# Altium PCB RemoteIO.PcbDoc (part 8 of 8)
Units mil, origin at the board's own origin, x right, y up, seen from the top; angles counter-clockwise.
Board outline 7874.02 x 2362.2 mil, 6 copper layers (Top Layer, GND1, Layer 2, PWR, GND2, Bottom Layer), stack 60.956 mil thick; 655 components, 447 nets, 2607 pads, 1444 vias.
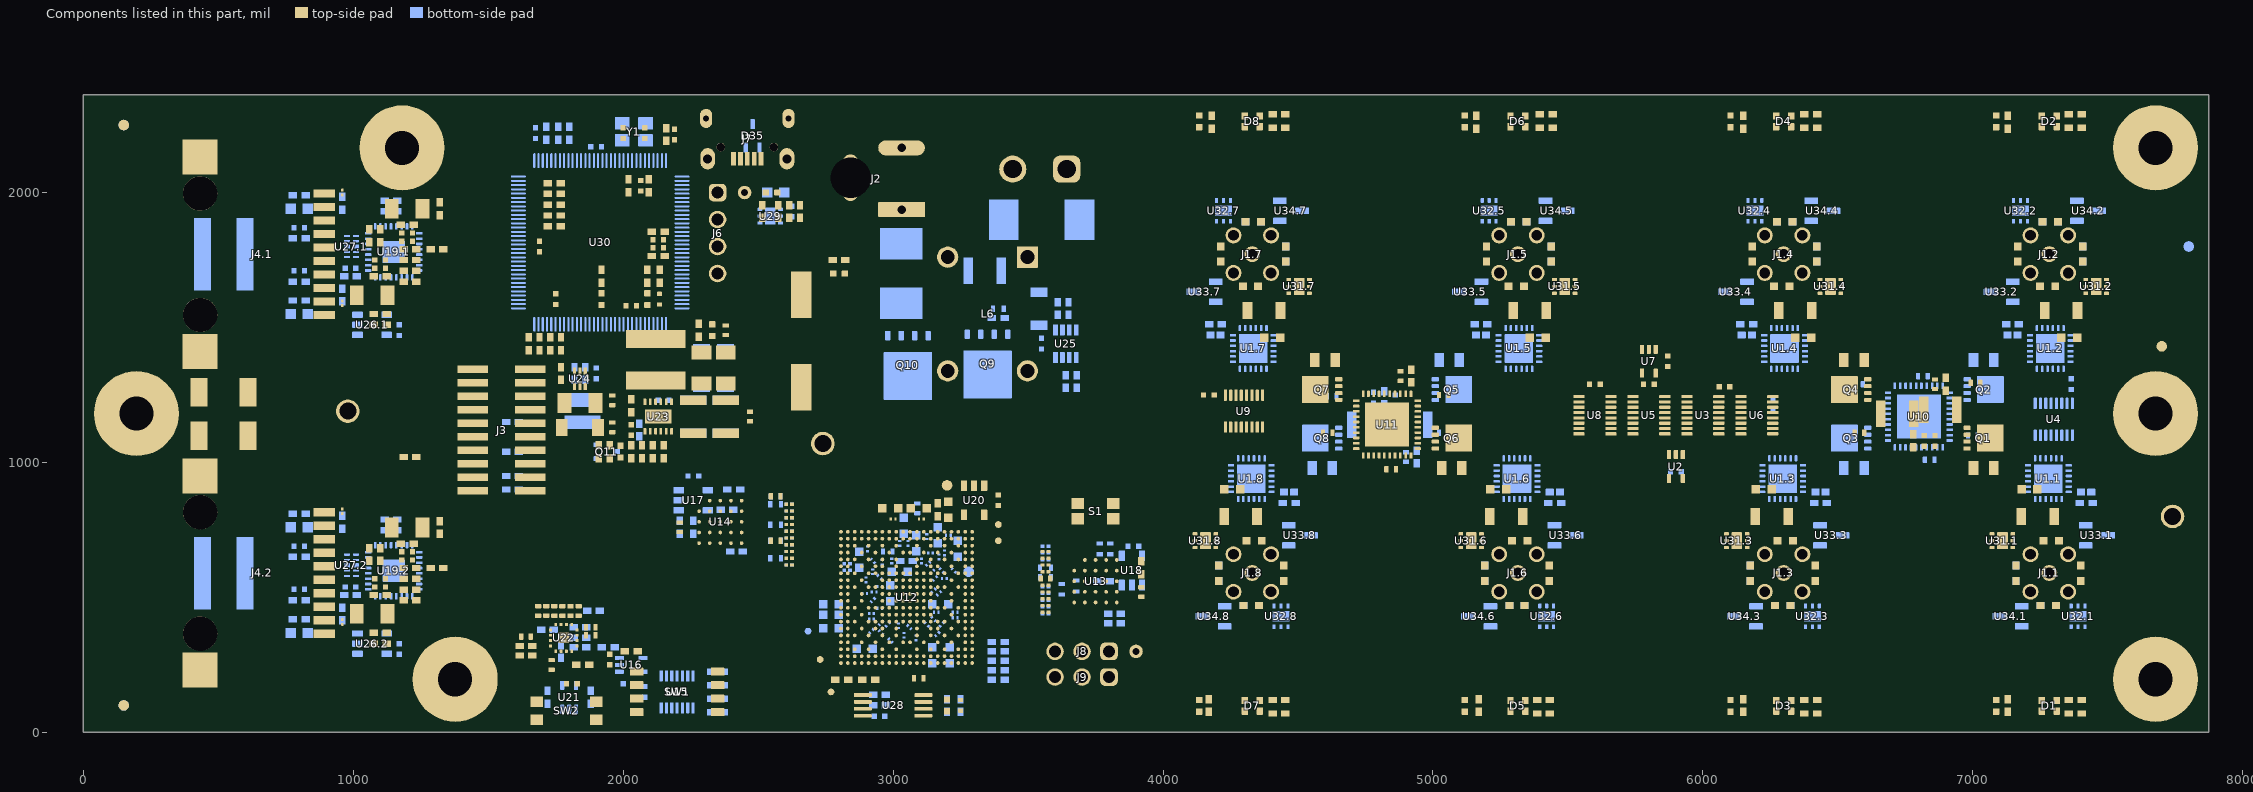
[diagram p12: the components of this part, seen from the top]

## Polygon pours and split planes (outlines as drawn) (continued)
NetQ3_1 on Bottom Layer "BOTTOM_LAYER_NETQ3_1_P293" (solid, remove dead copper, pour order 293): 6700,1130 6700,1090 6670,1090 6645,1065 6580,1065 6580,1140 6625,1140 6635,1130
24V on Bottom Layer "BOTTOM_LAYER_24V_P288" (solid, remove dead copper, pour order 288): 6700,1211.25 6700,1128.75 6590,1128.75 6590,1211.25
GND on Bottom Layer "BOTTOM_LAYER_GND_P286" (solid, remove dead copper, pour order 286): 5000,1410 5045,1410 5045,1330 5000,1330
L+5 on Bottom Layer "BOTTOM_LAYER_L+5_P284" (solid, remove dead copper, pour order 284): 5045,1205 5150,1205 5150,1410 5075,1410 5075,1350 5045,1320
NetQ5_1 on Bottom Layer "BOTTOM_LAYER_NETQ5_1_P283" (solid, remove dead copper, pour order 283): 4985,1290 5040,1290 5040,1205 4985,1205
GND on Bottom Layer "BOTTOM_LAYER_GND_P280" (solid, remove dead copper, pour order 280): 4740,1235 4925,1235 4965,1195 4965,1020 4745,1020 4740,1025
CS1 on Bottom Layer "BOTTOM_LAYER_CS1_P278" (solid, remove dead copper, pour order 278): 5045,1140 5145,1140 5145,1040 5045,1040
NetQ6_1 on Bottom Layer "BOTTOM_LAYER_NETQ6_1_P276" (solid, remove dead copper, pour order 276): 5010,1135 5010,1080 5045,1080 5045,1135
24V on Bottom Layer "BOTTOM_LAYER_24V_P275" (solid, remove dead copper, pour order 275): 5010,1090 5010,1135 5020,1145 5045,1145 5045,1195 4960,1195 4960,1090
24V on Bottom Layer "BOTTOM_LAYER_24V_P271" (solid, remove dead copper, pour order 271): 4635,1195 4635,1135 4660,1135 4680,1115 4680,1085 4700,1085 4740,1085 4740,1195
GND on Bottom Layer "BOTTOM_LAYER_GND_P269" (solid, remove dead copper, pour order 269): 4670,1010.14 4670,950.14 4605,950.14 4605,1010.14
L+8 on Bottom Layer "BOTTOM_LAYER_L+8_P267" (solid, remove dead copper, pour order 267): 4515,1140 4615,1140 4615,1040 4580,1005 4580,950 4515,950
NetQ8_1 on Bottom Layer "BOTTOM_LAYER_NETQ8_1_P265" (solid, remove dead copper, pour order 265): 4620,1145 4650,1145 4665,1130 4675,1120 4675,1065 4620,1065
L+7 on Bottom Layer "BOTTOM_LAYER_L+7_P087" (solid, remove dead copper, pour order 87): 4515,1220 4620,1220 4620,1320 4515,1320
NetQ7_1 on Bottom Layer "BOTTOM_LAYER_NETQ7_1_P263" (solid, remove dead copper, pour order 263): 4625,1275 4675,1275 4700,1250 4700,1205 4645,1205 4625,1225
GND on Bottom Layer "BOTTOM_LAYER_GND_P262" (solid, remove dead copper, pour order 262): 2470,1850 2470,2025 2675,2025 2675,1850
+3V3_XDS110 on Bottom Layer "BOTTOM_LAYER_+3V3_XDS110_P088" (solid, remove dead copper, pour order 88): 2025,1480 2070,1480 2070,1570 2025,1570
GND on Bottom Layer "BOTTOM_LAYER_GND_P256" (solid, remove dead copper, pour order 256): 7020,1410 7020,1350 6960,1350 6960,1410
L+2 on Bottom Layer "BOTTOM_LAYER_L+2_P252" (solid, remove dead copper, pour order 252): 7015,1220 7120,1220 7120,1410 7040,1410 7040,1345 7015,1320
NetQ2_1 on Bottom Layer "BOTTOM_LAYER_NETQ2_1_P251" (solid, remove dead copper, pour order 251): 6900,1245 6925,1245 6935,1255 6935,1275 6950,1290 7000,1290 7000,1225 6985,1210 6900,1210
24V on Bottom Layer "BOTTOM_LAYER_24V_P250" (solid, remove dead copper, pour order 250): 7005,1210 7005,1127.5 6895,1127.5 6895,1210
L+1 on Bottom Layer "BOTTOM_LAYER_L+1_P247" (solid, remove dead copper, pour order 247): 7005,1145 7115,1145 7115,1040 7005,1040
NetQ1_1 on Bottom Layer "BOTTOM_LAYER_NETQ1_1_P245" (solid, remove dead copper, pour order 245): 6900,1134.05 6900,1095 6930,1095 6945,1080 7000,1080 7000,1134.05
NetJ1.8_4 on Bottom Layer "BOTTOM_LAYER_NETJ1.8_4_P184" (solid, remove dead copper, pour order 184): 4192.24,375 4327.24,375 4327.24,550 4192.24,550
GND on Bottom Layer "BOTTOM_LAYER_GND_P200" (solid, remove dead copper, pour order 200): 4332.24,375 4502.24,375 4502.24,585 4332.24,585
NetU31.8_4 on Bottom Layer "BOTTOM_LAYER_NETU31.8_4_P102" (solid, remove dead copper, pour order 102): 4397.24,405 4397.24,375 4187.24,375 4187.24,595 4139.74,642.5 4139.74,750 4077.24,750 4077.24,400 4077.24,330 4497.24,330 4577.24,410 4577.24,745 4507.24,745 4507.24,425 4487.24,405
NetJ1.8_2 on Bottom Layer "BOTTOM_LAYER_NETJ1.8_2_P216" (solid, remove dead copper, pour order 216): 4342.24,600 4502.24,600 4502.24,785 4342.24,785
NetJ1.8_2 on Bottom Layer "BOTTOM_LAYER_NETJ1.8_2_P242" (solid, remove dead copper, pour order 242): 4272.24,880 4307.24,880 4307.24,800 4272.24,800
NetJ1.7_4 on Bottom Layer "BOTTOM_LAYER_NETJ1.7_4_P183" (solid, remove dead copper, pour order 183): 4469.17,1987.2 4334.17,1987.2 4334.17,1812.2 4469.17,1812.2
GND on Bottom Layer "BOTTOM_LAYER_GND_P199" (solid, remove dead copper, pour order 199): 4329.17,1987.2 4159.17,1987.2 4159.17,1777.2 4329.17,1777.2
NetU31.7_4 on Bottom Layer "BOTTOM_LAYER_NETU31.7_4_P101" (solid, remove dead copper, pour order 101): 4264.17,1957.2 4264.17,1987.2 4474.17,1987.2 4474.17,1767.2 4521.67,1719.7 4521.67,1612.2 4584.17,1612.2 4584.17,1962.2 4584.17,2032.2 4164.17,2032.2 4084.17,1952.2 4084.17,1617.2 4154.17,1617.2 4154.17,1937.2 4174.17,1957.2
NetJ1.7_2 on Bottom Layer "BOTTOM_LAYER_NETJ1.7_2_P215" (solid, remove dead copper, pour order 215): 4319.17,1762.2 4159.17,1762.2 4159.17,1577.2 4319.17,1577.2
NetJ1.7_2 on Bottom Layer "BOTTOM_LAYER_NETJ1.7_2_P241" (solid, remove dead copper, pour order 241): 4389.17,1482.2 4354.17,1482.2 4354.17,1562.2 4389.17,1562.2
NetJ1.6_4 on Bottom Layer "BOTTOM_LAYER_NETJ1.6_4_P182" (solid, remove dead copper, pour order 182): 5176.5,375 5311.5,375 5311.5,550 5176.5,550
GND on Bottom Layer "BOTTOM_LAYER_GND_P190" (solid, remove dead copper, pour order 190): 5316.5,375 5486.5,375 5486.5,585 5316.5,585
NetU31.6_4 on Bottom Layer "BOTTOM_LAYER_NETU31.6_4_P098" (solid, remove dead copper, pour order 98): 5381.5,405 5381.5,375 5171.5,375 5171.5,595 5124,642.5 5124,750 5061.5,750 5061.5,400 5061.5,330 5481.5,330 5561.5,410 5561.5,745 5491.5,745 5491.5,425 5471.5,405
NetJ1.6_2 on Bottom Layer "BOTTOM_LAYER_NETJ1.6_2_P206" (solid, remove dead copper, pour order 206): 5326.5,600 5486.5,600 5486.5,785 5326.5,785
NetJ1.6_2 on Bottom Layer "BOTTOM_LAYER_NETJ1.6_2_P222" (solid, remove dead copper, pour order 222): 5256.5,880 5291.5,880 5291.5,800 5256.5,800
NetJ1.5_4 on Bottom Layer "BOTTOM_LAYER_NETJ1.5_4_P181" (solid, remove dead copper, pour order 181): 5453.43,1987.2 5318.43,1987.2 5318.43,1812.2 5453.43,1812.2
GND on Bottom Layer "BOTTOM_LAYER_GND_P189" (solid, remove dead copper, pour order 189): 5313.43,1987.2 5143.43,1987.2 5143.43,1777.2 5313.43,1777.2
NetU31.5_4 on Bottom Layer "BOTTOM_LAYER_NETU31.5_4_P093" (solid, remove dead copper, pour order 93): 5248.43,1957.2 5248.43,1987.2 5458.43,1987.2 5458.43,1767.2 5505.93,1719.7 5505.93,1612.2 5568.43,1612.2 5568.43,1962.2 5568.43,2032.2 5148.43,2032.2 5068.43,1952.2 5068.43,1617.2 5138.43,1617.2 5138.43,1937.2 5158.43,1957.2
NetJ1.5_2 on Bottom Layer "BOTTOM_LAYER_NETJ1.5_2_P205" (solid, remove dead copper, pour order 205): 5303.43,1762.2 5143.43,1762.2 5143.43,1577.2 5303.43,1577.2
NetJ1.5_2 on Bottom Layer "BOTTOM_LAYER_NETJ1.5_2_P221" (solid, remove dead copper, pour order 221): 5373.43,1482.2 5338.43,1482.2 5338.43,1562.2 5373.43,1562.2
NetJ1.4_4 on Bottom Layer "BOTTOM_LAYER_NETJ1.4_4_P180" (solid, remove dead copper, pour order 180): 6437.68,1987.2 6302.68,1987.2 6302.68,1812.2 6437.68,1812.2
GND on Bottom Layer "BOTTOM_LAYER_GND_P188" (solid, remove dead copper, pour order 188): 6297.68,1987.2 6127.68,1987.2 6127.68,1777.2 6297.68,1777.2
NetU31.4_4 on Bottom Layer "BOTTOM_LAYER_NETU31.4_4_P092" (solid, remove dead copper, pour order 92): 6232.68,1957.2 6232.68,1987.2 6442.68,1987.2 6442.68,1767.2 6490.18,1719.7 6490.18,1612.2 6552.68,1612.2 6552.68,1962.2 6552.68,2032.2 6132.68,2032.2 6052.68,1952.2 6052.68,1617.2 6122.68,1617.2 6122.68,1937.2 6142.68,1957.2
NetJ1.4_2 on Bottom Layer "BOTTOM_LAYER_NETJ1.4_2_P204" (solid, remove dead copper, pour order 204): 6287.68,1762.2 6127.68,1762.2 6127.68,1577.2 6287.68,1577.2
NetJ1.4_2 on Bottom Layer "BOTTOM_LAYER_NETJ1.4_2_P220" (solid, remove dead copper, pour order 220): 6357.68,1482.2 6322.68,1482.2 6322.68,1562.2 6357.68,1562.2
NetJ1.3_4 on Bottom Layer "BOTTOM_LAYER_NETJ1.3_4_P179" (solid, remove dead copper, pour order 179): 6160.75,375 6295.75,375 6295.75,550 6160.75,550
GND on Bottom Layer "BOTTOM_LAYER_GND_P187" (solid, remove dead copper, pour order 187): 6300.75,375 6470.75,375 6470.75,585 6300.75,585
NetU31.3_4 on Bottom Layer "BOTTOM_LAYER_NETU31.3_4_P091" (solid, remove dead copper, pour order 91): 6365.75,405 6365.75,375 6155.75,375 6155.75,595 6108.25,642.5 6108.25,750 6045.75,750 6045.75,400 6045.75,330 6465.75,330 6545.75,410 6545.75,745 6475.75,745 6475.75,425 6455.75,405
NetJ1.3_2 on Bottom Layer "BOTTOM_LAYER_NETJ1.3_2_P203" (solid, remove dead copper, pour order 203): 6310.75,600 6470.75,600 6470.75,785 6310.75,785
NetJ1.3_2 on Bottom Layer "BOTTOM_LAYER_NETJ1.3_2_P219" (solid, remove dead copper, pour order 219): 6240.75,880 6275.75,880 6275.75,800 6240.75,800
NetJ1.2_4 on Bottom Layer "BOTTOM_LAYER_NETJ1.2_4_P178" (solid, remove dead copper, pour order 178): 7421.93,1987.2 7286.93,1987.2 7286.93,1812.2 7421.93,1812.2
GND on Bottom Layer "BOTTOM_LAYER_GND_P186" (solid, remove dead copper, pour order 186): 7281.93,1987.2 7111.93,1987.2 7111.93,1777.2 7281.93,1777.2
NetU31.2_4 on Bottom Layer "BOTTOM_LAYER_NETU31.2_4_P090" (solid, remove dead copper, pour order 90): 7216.93,1957.2 7216.93,1987.2 7426.93,1987.2 7426.93,1767.2 7474.43,1719.7 7474.43,1612.2 7536.93,1612.2 7536.93,1962.2 7536.93,2032.2 7116.93,2032.2 7036.93,1952.2 7036.93,1617.2 7106.93,1617.2 7106.93,1937.2 7126.93,1957.2
NetJ1.2_2 on Bottom Layer "BOTTOM_LAYER_NETJ1.2_2_P202" (solid, remove dead copper, pour order 202): 7271.93,1762.2 7111.93,1762.2 7111.93,1577.2 7271.93,1577.2
NetJ1.2_2 on Bottom Layer "BOTTOM_LAYER_NETJ1.2_2_P218" (solid, remove dead copper, pour order 218): 7341.93,1482.2 7306.93,1482.2 7306.93,1562.2 7341.93,1562.2
NetJ1.1_2 on Bottom Layer "BOTTOM_LAYER_NETJ1.1_2_P217" (solid, remove dead copper, pour order 217): 7225,880 7260,880 7260,800 7225,800
NetJ1.1_2 on Bottom Layer "BOTTOM_LAYER_NETJ1.1_2_P201" (solid, remove dead copper, pour order 201): 7295,600 7455,600 7455,785 7295,785
NetU31.1_4 on Bottom Layer "BOTTOM_LAYER_NETU31.1_4_P089" (solid, remove dead copper, pour order 89): 7350,405 7350,375 7140,375 7140,595 7092.5,642.5 7092.5,750 7030,750 7030,400 7030,330 7450,330 7530,410 7530,745 7450,745 7450,440 7415,405
GND on Bottom Layer "BOTTOM_LAYER_GND_P185" (solid, remove dead copper, pour order 185): 7285,375 7455,375 7455,585 7285,585
NetJ1.1_4 on Bottom Layer "BOTTOM_LAYER_NETJ1.1_4_P177" (solid, remove dead copper, pour order 177): 7145,375 7280,375 7280,550 7145,550
NetC114_2 on Bottom Layer "BOTTOM_LAYER_NETC114_2_P176" (solid, remove dead copper, pour order 176): 1780,1175 1780,1120 1820,1120 1820,1095 1920,1095 1920,1175
GND on Bottom Layer "BOTTOM_LAYER_GND_P175" (solid, remove dead copper, pour order 175): 565,1910 680,1910 680,450 565,450
NetC104_2 on Bottom Layer "BOTTOM_LAYER_NETC104_2_P150" (solid, remove dead copper, pour order 150): 2440,1130 2440,1070 2160,1070 2135,1095 2135,1130
NetC108_1 on Bottom Layer "BOTTOM_LAYER_NETC108_1_P143" (solid, remove dead copper, pour order 143): 2250,1445 2420,1445 2420,1365 2250,1365
GND on Bottom Layer "BOTTOM_LAYER_GND_P141" (solid, remove dead copper, pour order 141): 2080,1200 2080,1140 2210,1140 2255,1185 2440,1185 2440,1340 2240,1340 2240,1260 2200,1260 2200,1200
24V on Bottom Layer "BOTTOM_LAYER_24V_P134" (solid, remove dead copper, pour order 134): 2600,1425 2600.82,1425.82 3150,1425.82 3150,1185 2600,1185
GND on Bottom Layer "BOTTOM_LAYER_GND_P132" (solid, remove dead copper, pour order 132): 3500,1650 3500,1580 3580,1580 3580,1650
NetQ9_1 on Bottom Layer "BOTTOM_LAYER_NETQ9_1_P086" (solid, remove dead copper, pour order 86): 2965,1515 2965,1450 3400,1450 3400,1515
NetC117_2 on Bottom Layer "BOTTOM_LAYER_NETC117_2_P131" (solid, remove dead copper, pour order 131): 3160,1450 3160,1230 3450,1230 3450,1385 3480,1385 3535,1440 3627.2,1440 3627.2,1570 3540,1570 3450,1480 3450,1450
NetC120_2 on Bottom Layer "BOTTOM_LAYER_NETC120_2_P122" (solid, remove dead copper, pour order 122): 2935,1525 3115,1525 3175,1525 3315,1665 3315,1800 3150,1800 3150,1750 3100,1700 2935,1700
NetC120_1 on Bottom Layer "BOTTOM_LAYER_NETC120_1_P121" (solid, remove dead copper, pour order 121): 23 vertices, not listed, extent 2800,1650 3765,2335
NetD25_2 on Bottom Layer "BOTTOM_LAYER_NETD25_2_P118" (solid, remove dead copper, pour order 118): 2945,1750 3110,1750 3110,1800 3135,1825 3485,1825 3510,1850 3510,2110 3470,2150 3200,2150 3050,2000 2945,2000 2935,1990 2935,1760
GND on Bottom Layer "BOTTOM_LAYER_GND_P103" (solid, remove dead copper, pour order 103): 1715,450 1840,450 1840,285 1715,285
3V3 on Bottom Layer "BOTTOM_LAYER_3V3_P106" (solid, remove dead copper, pour order 106): 3020.75,632.05 3020.75,875 2965,875 2965,632.05
Vcore on Bottom Layer "BOTTOM_LAYER_VCORE_P108" (solid, remove dead copper, pour order 108): 3060,820 3105,820 3105,780 3080,755 3060,755
1V25 on Bottom Layer "BOTTOM_LAYER_1V25_P117" (solid, remove dead copper, pour order 117): 3065,890 3140,890 3145,885 3145,835 3140,830 3065,830 3060,835 3060,885
Vcore on Bottom Layer "BOTTOM_LAYER_VCORE_P115" (solid, remove dead copper, pour order 115): 2950,530 2920,530 2910,540 2910,580 2925,595 2980,595 2985,600 2985,580 2955,580 2950,575
GND on Bottom Layer "BOTTOM_LAYER_GND_P116" (solid, remove dead copper, pour order 116): 2720,825 3310,825 3310,210 2720,210
3V3 on PWR "PWR_3V3_P149" (solid, remove dead copper, pour order 149): 26 vertices, not listed, extent 920,0 7874.02,2362.2
24V on PWR "PWR_24V_P270" (solid, remove dead copper, pour order 270): 3185,930 3185,1020 3120,1085 2455,1085 2455,1280 3565,1280 3565,1515 3850,1515 3850,2150 7565,2150 7565,300 4050,300 4050,930 3805,930
+3V3_XDS110 on PWR "PWR_+3V3_XDS110_P254" (solid, remove dead copper, pour order 254): 1550,2300 2750,2300 2750,1550 1550,1550
1V25 on PWR "PWR_1V25_P085" (solid, remove dead copper, pour order 85): 1945,1135 2010,1135 2010,1090 2030,1070 3090,1070 3145,1015 3145,840 3080,840 3005,915 1955,915 1945,925
24V on PWR "PWR_24V_P139" (solid, remove dead copper, pour order 139): 2455,1425.82 3150,1425.82 3150,1185 2455,1185
NetQ9_1 on PWR "PWR_NETQ9_1_P125" (solid, remove dead copper, pour order 125): 2965,1520 2965,1425 3395,1425 3395,1520
VDDS18 on PWR "PWR_VDDS18_P104" (solid, remove dead copper, pour order 104): 33 vertices, not listed, extent 2795,255 3310,680
VDDSHV on PWR "PWR_VDDSHV_P110" (solid, remove dead copper, pour order 110): 2855,700 3245,700 3245,325 2855,325
VDDA18 on PWR "PWR_VDDA18_P097" (solid, remove dead copper, pour order 97): 2905,695 2905,630 2940,630 2940,670 2965,670 2965,630 3210,630 3210,695
L+1 on Layer 2 "LAYER_2_L+1_P303" (solid, remove dead copper, pour order 303): 7015,1145 7015,670 7085,600 7255,600 7265,610 7265,745 7260,745 7140,865 7140,1145
L+6 on Layer 2 "LAYER_2_L+6_P299" (solid, remove dead copper, pour order 299): 5050,1140 5050,800 5120,730 5120,670 5185,605 5285,605 5290,610 5290,795 5150,935 5150,1140
L+5 on Layer 2 "LAYER_2_L+5_P287" (solid, remove dead copper, pour order 287): 5050,1220 5145,1220 5145,1330 5330,1515 5330,1600 5165,1600 5050,1485
L+8 on Layer 2 "LAYER_2_L+8_P268" (solid, remove dead copper, pour order 268): 4315,840 4315,760 4320,755 4620,755 4620,1105 4505,1105 4505,1030
L+7 on Layer 2 "LAYER_2_L+7_P261" (solid, remove dead copper, pour order 261): 4615,1220 4615,1545 4525,1635 4525,1710 4480,1755 4350,1755 4350,1655 4515,1490 4515,1220
24V on Layer 2 "LAYER_2_24V_P124" (solid, remove dead copper, pour order 124): 2600,1425 2600.82,1425.82 3150,1425.82 3150,1185 2600,1185
Vcore on Layer 2 "LAYER_2_VCORE_P095" (solid, remove dead copper, pour order 95): 2915,625 2900,610 2900,353.81 2928.81,325 3162.32,325 3190,352.68 3190,625 3190,710 3095,805 3065,805 2940,680 2940,650
VDDS18 on Layer 2 "LAYER_2_VDDS18_P094" (solid, remove dead copper, pour order 94): 17 vertices, not listed, extent 2820,275 3280,700
GND on GND2 "GND2_GND_P298" (solid, remove dead copper, pour order 298): 2790,2362.2 2790,1635 2900,1635 2900,1500 3395,1500 3395,1635 3800,1635 3800,2362.2 7875,2362.2 7875,0 745.98,0 745.98,2362.2
24V on GND2 "GND2_24V_P126" (solid, remove dead copper, pour order 126): 2600,1425 2600.82,1425.82 3150,1425.82 3150,1185 2600,1185
CS1 on GND2 "GND2_CS1_P111" (solid, remove dead copper, pour order 111): 2165,980 2685,980 2685,590 2165,590
GND on GND1 "GND1_GND_P229" (solid, remove dead copper, pour order 229): 2790,2362.2 2790,1635 2900,1635 2900,1500 3400,1500 3400,1635 3800,1635 3800,2362.2 7874.02,2362.2 7874.02,0 635,0 635,2362.2
24V on GND1 "GND1_24V_P123" (solid, remove dead copper, pour order 123): 2600,1425 2600.82,1425.82 3150,1425.82 3150,1185 2600,1185

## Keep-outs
Keep-Out Layer:
  text ".Layer_Name" at 577,-858.49 h60

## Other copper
Top Layer:
  text "Eth 1" at 590.04,2130.58 h100
  text "GND" at 3540,1911.08 h100
  text "+" at 3306,1889.34 h100
  text "24V 5A max" at 2758.92,1784.92 h100 r90
  text "IO 7" at 4796.16,1692.85 h100 r90
  text "IO 5" at 5780.41,1692.62 h100 r90
  text "IO 4" at 6764.67,1693 h100 r90
  text "IO 2" at 7748.92,1693.08 h100 r90
  text "24V 9A max" at 3930,1600 h100 r90
  text "IO 1" at 7748.92,517.93 h100 r90
  text "IO 8" at 4796.16,511.69 h100 r90
  text "IO 6" at 5780.41,511.77 h100 r90
  text "IO 3" at 6764.62,511.75 h100 r90
  text "Eth 2" at 590.04,180.58 h100
  text ".Layer_Name" at 577,-858.49 h60
Bottom Layer:
  text ".Layer_Name" at 577,-858.49 h60

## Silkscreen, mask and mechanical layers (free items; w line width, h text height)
Top Overlay:
  circle w10: c3670,640 r10
  lines w10: 3630,400 3630.03,400.03 3869.97,400.03 3870,400.06 3870,720 3630,720 3630,400
  text "XDS110" at 2264,2096 h30 r90
  text "JTAG" at 1496,816 h30
  text "Bootmode" at 2106,296 h30
  text "'.PRJ_Number'.PCB_Rev" at 470,50 h108.27
  text "RUN" at 3389.13,50.03 h80 r90
  text "ERR" at 3460,50.03 h80 r90
  text "Reset" at 1634,36 h30 r90
  text ".Layer_Name" at 577,-858.49 h60
Bottom Overlay:
  text ".Layer_Name" at 577,-858.49 h60
Top Paste:
  text ".Layer_Name" at 577,-858.49 h60
Bottom Paste:
  text ".Layer_Name" at 577,-858.49 h60
Top Solder:
  text "Eth 1" at 590.04,2130.58 h100
  text "GND" at 3540,1911.08 h100
  text "+" at 3306,1889.34 h100
  text "24V 5A max" at 2758.92,1784.92 h100 r90
  text "IO 7" at 4796.16,1692.85 h100 r90
  text "IO 5" at 5780.41,1692.62 h100 r90
  text "IO 4" at 6764.67,1693 h100 r90
  text "IO 2" at 7748.92,1693.08 h100 r90
  text "24V 9A max" at 3928.92,1599.92 h100 r90
  text "IO 1" at 7748.92,517.93 h100 r90
  text "IO 8" at 4796.16,511.69 h100 r90
  text "IO 6" at 5780.41,511.77 h100 r90
  text "IO 3" at 6764.62,511.75 h100 r90
  text "Eth 2" at 590.04,180.58 h100
  text ".Layer_Name" at 577,-858.49 h60
  text ".Layer_Name" at 577,-858.49 h60
Bottom Solder:
  text ".Layer_Name" at 577,-858.49 h60
Drill Guide:
  text ".Layer_Name" at 577,-858.49 h60
M1 Board Outline:
  the board outline again, w10
  text ".Layer_Name" at 577,-858.49 h60
M2 Board Dimensions:
  rectangle: 0,-275 125,-150
  rectangle: 125,-400 500,-275
  lines w7: 0,-275 1000,-275 ; 125,-400 125,-150 ; 250,-400 250,-150 ; 500,-400 500,-150 ; 750,-400 750,-150 ; 0,-400 1000,-400 1000,-150 0,-150 0,-400
  text ".Layer_Name" at 577,-858.49 h60
M3 3D STEP Top:
  text ".Layer_Name" at 577,-858.49 h60
M4 3D STEP Bottom:
  text ".Layer_Name" at 577,-858.49 h60
M5 Assembly Top:
  lines w10: -292,-930.17 6308,-930.17 ; -292,-726.83 6310,-726.83 ; -292,-523.5 -292,-1133.5 3713,-1133.5 6310,-1133.5 6310,-523.5 -291.5,-523.5 -291.5,-1133.5 1284,-1133.5 ; 2173,-1133.5 2173,-523.5 ; 3440,-726.83 3440,-523.5 ; 4280,-726.83 4280,-523.5 ; 4902,-1140 4902,-937.17
  text "COMPONENTS MARKED 'DNP' SHOULD NOT BE POPULATED." at 1153.5,-318.5 h60
  text "ASSEMBLY VARIANT:" at 1153,-434 h60
  text ".VariantName" at 2189,-434 h60
  text "PCB VIEWED FROM TOP SIDE" at -228.5,-655.67 h60
  text "BOARD #:" at 2248,-655.67 h60
  text ".PRJ_Number" at 2793.5,-655.67 h60
  text "REV:" at 3638,-655.67 h60
  text ".PCB_Rev" at 3929.5,-655.67 h60
  text "SVN REV:" at 4476,-655.67 h60
  text ".VersionControl_RevNumber" at 4982,-655.67 h60
  text "TID #:" at 2248,-859 h60
  text ".TID" at 2793.5,-859 h60
  text "PLOT NAME =" at -228.5,-1064.34 h60
  text ".plot_File_Name" at 577,-1064.34 h60
  text "GENERATED    :" at 2250,-1064.34 h60
  text ".Print_Date" at 3119.5,-1064.34 h60
  text ".Print_Time" at 3848.5,-1064.34 h60
  text "TEXAS INSTRUMENTS" at 5113,-1064.34 h60
M6 Assembly Bottom:
  lines w10: -292.5,-727.33 6309.5,-727.33 ; -290.5,-930.67 6309.5,-930.67 ; 1115.5,-1140.5 1115.5,-937.67 ; 1737.5,-727.33 1737.5,-524 ; 2577.5,-727.33 2577.5,-524 ; 3844.5,-1134 3844.5,-524 ; 4733.5,-1134 6309,-1134 6309,-524 -292.5,-524 -292.5,-1134 2304.5,-1134 6309.5,-1134 6309.5,-524
  text "COMPONENTS MARKED 'DNP' SHOULD NOT BE POPULATED." at 6102,-318 h60
  text ".VariantName" at 5058,-434 h60
  text "ASSEMBLY VARIANT:" at 6097,-434 h60
  text ".VersionControl_RevNumber" at 1035.5,-656.17 h60
  text "SVN REV:" at 1541.5,-656.17 h60
  text ".PCB_Rev" at 2088,-656.17 h60
  text "REV:" at 2379.5,-656.17 h60
  text ".PRJ_Number" at 3224,-656.17 h60
  text "BOARD #:" at 3769.5,-656.17 h60
  text "PCB VIEWED FROM BOTTOM SIDE" at 6246,-656.17 h60
  text ".TID" at 3224,-859.5 h60
  text "TID #:" at 3769.5,-859.5 h60
  text "TEXAS INSTRUMENTS" at 904.5,-1064.84 h60
  text ".Print_Time" at 2169,-1064.84 h60
  text ".Print_Date" at 2898,-1064.84 h60
  text "GENERATED    :" at 3767.5,-1064.84 h60
  text ".plot_File_Name" at 5440.5,-1064.84 h60
  text "PLOT NAME =" at 6246,-1064.84 h60
M9 Title Sheet:
  drawing of 57 lines, arcs and shapes, not listed
  text "1" at 739.84,8036.5 h70
  text "2" at 3235.5,8036.5 h70
  text "3" at 5724.84,8036.5 h70
  text "4" at 8231.51,8036.5 h70
  text "5" at 10730.5,8036.5 h70
  text "6" at 13235.5,8036.5 h70
  text "A" at -416.5,6893.5 h70
  text "A" at 14383.5,6893.5 h70
  text "B" at -416.5,4513.5 h70
  text "B" at 14383.5,4513.5 h70
  text "C" at -416.5,2138.5 h70
  text "C" at 14383.5,2138.5 h70
  text "PROJECT TITLE:" at 11343.5,277.5 h45
  text ".PRJ_Title" at 11393.5,144.17 h70
  text "DESIGNED FOR:" at 11343.5,-23.5 h45
  text ".PRJ_Customer" at 11393.5,-163.5 h70
  text "D" at -416.5,-231.5 h70
  text "D" at 14383.5,-231.5 h70
  text "FILE NAME:" at 11343.5,-323.5 h45
  text ".PCB_File_Name_No_Path" at 11393.5,-443.5 h70
  text "Texas Instruments (TI) and/or its licensors do not warrant the accuracy or completeness of this specification" at 6374,-605.34 h45
  text "ENGINEER:" at 11343.5,-613.5 h45
  text "LAYOUT BY:" at 12848.5,-613.5 h45
  text "or any information contained therein. TI and/or its licensors do not warrant that this design will meet" at 6329.01,-718 h45
  text ".PRJ_Engineer" at 11393.5,-768.49 h70
  text ".PCB_Layout" at 12899,-768.49 h70
  text "the specifications, will be suitable for your application or fit for any particular purpose, or will operate in" at 6329.01,-830.67 h45
  text ".Layer_Name" at 577,-858.49 h60
  text "ALTIUM DESIGNER VERSION:" at 12848.5,-923.5 h45
  text "an implementation. TI and/or its licensors do not warrant that the design is production worthy. You should" at 6329.01,-943.33 h45
  text "completely validate and test your design implementation to confirm the system functionality for your application." at 6374,-1056 h45
  text ".print_Scale" at 11393.5,-1056.83 h70
  text ".Application_BuildNumber" at 12899,-1056.83 h70
  text "1" at 739.84,-1263.5 h70
  text "2" at 3235.5,-1263.5 h70
  text "3" at 5724.84,-1263.5 h70
  text "4" at 8231.51,-1263.5 h70
  text "5" at 10730.5,-1263.5 h70
  text "6" at 13235.5,-1263.5 h70
M10 Fab Notes:
  drawing of 189 lines, arcs and shapes, not listed
  text "DESIGN INFORMATION" at 12382.02,6356.17 h60
  text "MIN. TRACK WIDTH:" at 11737.46,6224.05 h60
  text "4" at 12833.7,6224.05 h60
  text "MIL" at 12988.46,6224.05 h60
  text "4" at 12667.32,6102.36 h60
  text "MIN. CLEARANCE:" at 11737.46,6099.92 h60
  text "MIL" at 12988.46,6099.92 h60
  text "MIN. VIA PAD SIZE:" at 11737.46,5975.8 h60
  text "18" at 12803.71,5975.8 h60
  text "MIL" at 12988.46,5975.8 h60
  text "0.05mm (2MIL)" at 12432.46,5845.9 h60
  text "MINIMUM ANNULAR RING" at 11408.23,5837.67 h60
  text "EXTERNAL" at 13140.46,5837.67 h60
  text "PER" at 11608.23,5727.55 h60
  text "IPC-D-275 CLASS 2 LEVEL C" at 11828.23,5727.54 h60
  text "MIL, HOLES" at 13316.46,5627.07 h60
  text "+/-" at 12924,5618.48 h60
  text "+/-" at 13778,5618.48 h60
  text "REGISTRATION TOLERANCES:" at 11408.23,5617.42 h60
  text "METAL" at 12608,5617.42 h60
  text "5" at 13184.2,5617.42 h60
  text "3" at 14017.2,5617.42 h60
  text "MIL" at 14133.46,5617.42 h60
  text "HOLE SIZE TOLERANCE (UNLESS OTHERWISE SPECIFIED):" at 11408.23,5519.1 h60
  text "+/-" at 13778,5516.23 h60
  text "3" at 14017.2,5515.17 h60
  text "MIL" at 14133.46,5515.17 h60
  text "MATERIAL:" at 11333.46,5377.52 h60
  text "FR-4 High Tg" at 12319.9,5249 h60
  text "X" at 12175.46,5241.01 h60
  text "FR-4" at 11754.46,5236.49 h60
  text "OTHER" at 13242.46,5236.49 h60
  text "62 MIL (1.6mm) +/-10%" at 12074.56,5093.46 h60
  text "X" at 11954.46,5091.01 h60
  text "THICKNESS:" at 11408.23,5085.24 h60
  text "OTHER" at 13359.46,5085.24 h60
  text "TOLERANCE:" at 11408.23,4946.92 h60
  text "X" at 12256.46,4946.92 h60
  text "ANSI IPC-6012 TYPE 3 CLASS 2" at 12434.48,4946.92 h60
  text "OTHER +/-" at 12434.46,4802.73 h60
  text "BOW & TWIST:" at 11408.23,4657.54 h60
  text "X" at 12256.46,4657.54 h60
  text "ANSI IPC-6012 TYPE 3 CLASS 2" at 12434.48,4657.54 h60
  text "OTHER +/-" at 12434.46,4510.85 h60
  text "DRILLING:" at 11333.46,4380.23 h60
  text "NC_DRILL FILES" at 13094.46,4275.04 h60
  text "REFERENCE:" at 11408.23,4271.1 h60
  text "X" at 12065.46,4271.01 h60
  text "AS SHOWN" at 12243.46,4271.1 h60
  text "X" at 12966.46,4271.1 h60
  text "OTHER" at 13392.46,4128.85 h60
  text "PTH COPPER THICKNESS:" at 11407.91,4125.32 h60
  text "X" at 12547.14,4125.32 h60
  text "20-30 um" at 12675.14,4125.32 h60
  text "BOARD FINISH:" at 11333.46,3977.73 h60
  text "SILKSCREEN:" at 11488.68,3867.6 h60
  text "X" at 12446.46,3867.6 h60
  text "TOP" at 12563.46,3867.6 h60
  text "X" at 12956.46,3867.6 h60
  text "BOTTOM" at 13074.46,3867.6 h60
  text "SILKSCREEN COLOR:" at 11488.68,3712.41 h60
  text "X" at 12445.46,3712.41 h60
  text "WHITE" at 12563.46,3712.41 h60
  text "OTHER" at 13074.46,3712.41 h60
  text "X" at 12576.46,3568.96 h60
  text "GREEN" at 12694.46,3568.96 h60
  text "OTHER" at 13312.46,3568.96 h60
  text "SOLDER RESIST COLOR:" at 11488.68,3562.1 h60
  text "X" at 12576.46,3414.71 h60
  text "MATTE" at 12694.46,3414.71 h60
  text "SEMI-GLOSS" at 13312,3414.07 h60
  text "IMMERSION GOLD (ENIG)" at 12394.46,3241.94 h60
  text "ENEPIG" at 13732,3234.72 h60
  text "SURFACE FINISH:" at 11333.46,3233.72 h60
  text "X" at 12216.46,3233.72 h60
  text "IMM. TIN/SILVER OR EQUIV" at 11663,3096.4 h60
  text "OTHER" at 13094.46,3092.47 h60
  text "ARRAY/PANEL:" at 11333.46,2937.09 h60
  text "CUT AND TRIM PER M1 BOARD OUTLINE" at 12394.46,2928.87 h60
  text "N.C. ROUTE" at 12394.46,2792.9 h60
  text "X" at 13082.46,2792.9 h60
  text "V. SCORE" at 13260.46,2792.9 h60
  text "CERTIFICATION:" at 11333.46,2663.77 h60
  text "MATERIALS AND WORKMANSHIP FOR ALL PCBS" at 12058.46,2663.77 h60
  text "TO MEET OR EXCEED THE REQUIREMENTS OF:" at 12058.46,2569.71 h60
  text "X" at 11695.97,2441.08 h60
  text "ANSI IPC-A-600F CLASS ->" at 11823.96,2441.08 h60
  text "X" at 13471.97,2441.08 h60
  text "2" at 13581.96,2441.08 h60
  text "1" at 13266.96,2439.58 h60
  text "3" at 13935.96,2439.58 h60
  text "X" at 12507.97,2293.39 h60
  text "RoHS" at 12635.96,2293.39 h60
  text "OTHER" at 13280.36,2293.39 h60
  text "PER ORDER" at 13677.42,2293.39 h60
  text "ALL BOARDS MUST MEET OR EXCEED UL94-V0 REQUIREMENTS." at 11361,2139.57 h60
  text "PCB MUST BEAR THE UL94V-0 UL REGISTERED MATERIAL ID NUMBER" at 11361,2023.5 h60
  text "ADDITIONAL REQUIREMENTS:" at 11333.46,1854.08 h60
  text "MICROSECTION:" at 11408.23,1746.95 h60
  text "YES" at 12313.96,1746.95 h60
  text "REQUIRED" at 13175.46,1602.62 h60
  text "BARE BOARD ELEC. TEST:" at 11408.23,1599.76 h60
  text "NONE" at 12713.96,1599.76 h60
  text "X" at 13057.46,1599.76 h60
  text "PER ORDER" at 13767.46,1599.76 h60
  text "XX MIL VIAS REQUIRE NON-CONDUCTIVE FILL AND PLANARIZE" at 11576.38,1394.82 h59
  text "XX MIL VIAS REQUIRE CONDUCTIVE FILL AND PLANARIZE" at 11584.38,1290.84 h60
  text "OUTER 6.4 MIL TRACES REQUIRE 50 OHM SINGLE-ENDED IMPEDANCE" at 11583.39,1127.46 h58
  text "X" at 11459.75,1122.18 h60
  text "LAYER 2 & 3 (INNER LAYERS) XX MIL WIDE, XX MIL SPACE / TRACES REQUIRE 100 OHM DIFFERENTIAL IMPEDANCE" at 11575.39,891.74 h60
  text ".Layer_Name" at 577,-858.49 h60
M11 Gerber Information:
  lines w10: -292,-930.17 6308,-930.17 ; -292,-726.83 6310,-726.83 ; -292,-523.5 -292,-1133.5 3713,-1133.5 6310,-1133.5 6310,-523.5 -291.5,-523.5 -291.5,-1133.5 1284,-1133.5 ; 2173,-1133.5 2173,-523.5 ; 3440,-726.83 3440,-523.5 ; 4280,-726.83 4280,-523.5 ; 4902,-1140 4902,-937.17
  text "ALL ARTWORK VIEWED FROM TOP SIDE" at -228.5,-655.67 h60
  text "BOARD #:" at 2248,-655.67 h60
  text ".PRJ_Number" at 2793.5,-655.67 h60
  text "REV:" at 3638,-655.67 h60
  text ".PCB_Rev" at 3929.5,-655.67 h60
  text "SVN REV:" at 4476,-655.67 h60
  text ".VersionControl_RevNumber" at 4982,-655.67 h60
  text "LAYER NAME =" at -228.5,-858.49 h60
  text "TID #:" at 2248,-859 h60
  text ".TID" at 2793.5,-859 h60
  text "PLOT NAME =" at -228.5,-1064.34 h60
  text ".plot_File_Name" at 577,-1064.34 h60
  text "GENERATED    :" at 2250,-1064.34 h60
  text ".Print_Date" at 3119.5,-1064.34 h60
  text ".Print_Time" at 3848.5,-1064.34 h60
  text "TEXAS INSTRUMENTS" at 5113,-1064.34 h60
M12 Stackup:
  drawing of 399 lines, arcs and shapes, not listed
  text "Layer" at 6734.21,7814.1 h60
  text "Name" at 7144.13,7814.1 h60
  text "Material" at 8073.87,7814.1 h60
  text "Thickness" at 8933.64,7814.1 h60
  text "Constant" at 9583.47,7814.1 h60
  text "Board Layer Stack" at 10153.33,7814.1 h60
  text "Top Overlay" at 7144.13,7694.1 h60
  text "Top Solder" at 7144.13,7574.1 h60
  text "Solder Resist" at 8073.87,7574.1 h60
  text "0.40mil" at 8933.64,7574.1 h60
  text "3.5" at 9583.47,7574.1 h60
  text "1" at 6734.21,7454.1 h60
  text "Top Layer" at 7144.13,7454.1 h60
  text "1.40mil" at 8933.64,7454.1 h60
  text "Dielectric 1" at 7144.13,7334.1 h60
  text "PP-015" at 8073.87,7334.1 h60
  text "3.91mil" at 8933.64,7334.1 h60
  text "4.3" at 9583.47,7334.1 h60
  text "2" at 6734.21,7214.1 h60
  text "GND1" at 7144.13,7214.1 h60
  text "CF-004" at 8073.87,7214.1 h60
  text "0.69mil" at 8933.64,7214.1 h60
  text "Dielectric 2" at 7144.13,7094.1 h60
  text "Core-037" at 8073.87,7094.1 h60
  text "21.65mil" at 8933.64,7094.1 h60
  text "4.8" at 9583.47,7094.1 h60
  text "3" at 6734.21,6974.1 h60
  text "Layer 2" at 7144.13,6974.1 h60
  text "CF-004" at 8073.87,6974.1 h60
  text "0.69mil" at 8933.64,6974.1 h60
  text "Dielectric1" at 7144.13,6854.1 h60
  text "PP-016" at 8073.87,6854.1 h60
  text "4.28mil" at 8933.64,6854.1 h60
  text "4.4" at 9583.47,6854.1 h60
  text "4" at 6734.21,6734.1 h60
  text "PWR" at 7144.13,6734.1 h60
  text "CF-004" at 8073.87,6734.1 h60
  text "0.69mil" at 8933.64,6734.1 h60
  text "Dielectric 3" at 7144.13,6614.1 h60
  text "Core-037" at 8073.87,6614.1 h60
  text "21.65mil" at 8933.64,6614.1 h60
  text "4.8" at 9583.47,6614.1 h60
  text "5" at 6734.21,6494.1 h60
  text "GND2" at 7144.13,6494.1 h60
  text "CF-004" at 8073.87,6494.1 h60
  text "0.69mil" at 8933.64,6494.1 h60
  text "Dielectric 4" at 7144.13,6374.1 h60
  text "PP-015" at 8073.87,6374.1 h60
  text "3.91mil" at 8933.64,6374.1 h60
  text "4.3" at 9583.47,6374.1 h60
  text "6" at 6734.21,6254.1 h60
  text "Bottom Layer" at 7144.13,6254.1 h60
  text "1.40mil" at 8933.64,6254.1 h60
  text "Bottom Solder" at 7144.13,6134.1 h60
  text "Solder Resist" at 8073.87,6134.1 h60
  text "0.40mil" at 8933.64,6134.1 h60
  text "3.5" at 9583.47,6134.1 h60
  text "Bottom Overlay" at 7144.13,6014.1 h60
  text ".Layer_Name" at 577,-858.49 h60
M13 Component Bodies Top:
  text ".Layer_Name" at 577,-858.49 h60
M14 Component Bodies Bottom:
  text ".Layer_Name" at 577,-858.49 h60
M15 Courtyards Top:
  text ".Layer_Name" at 577,-858.49 h60
M16 Courtyards Bottom:
  text ".Layer_Name" at 577,-858.49 h60
Drill Drawing:
  drawing of 184 lines, arcs and shapes, not listed
  text "Symbol" at 3378.45,7781.6 h72
  text "Quantity" at 3679.03,7781.6 h72
  text "Finished Hole Size" at 4011.13,7781.6 h72
  text "Plated" at 4647.77,7781.6 h72
  text "Hole Type" at 4906.98,7781.6 h72
  text "Drill Layer Pair" at 5282.23,7781.6 h72
  text "Hole Tolerance" at 6006.84,7781.6 h72
  text "2" at 3679.03,7657.29 h60
  text "31.50mil (0.800mm)" at 4011.13,7657.29 h60
  text "NPTH" at 4647.77,7657.29 h60
  text "Round" at 4906.98,7657.29 h60
  text "Top Layer - Bottom Layer" at 5282.23,7657.29 h60
  text "4" at 3679.03,7532.98 h60
  text "126.77mil (3.220mm)" at 4011.13,7532.98 h60
  text "NPTH" at 4647.77,7532.98 h60
  text "Round" at 4906.98,7532.98 h60
  text "Top Layer - Bottom Layer" at 5282.23,7532.98 h60
  text "167" at 3679.03,7408.67 h60
  text "7.87mil (0.200mm)" at 4011.13,7408.67 h60
  text "PTH" at 4647.77,7408.67 h60
  text "Round" at 4906.98,7408.67 h60
  text "Top Layer - Bottom Layer" at 5282.23,7408.67 h60
  text "1277" at 3679.03,7284.35 h60
  text "8.00mil (0.203mm)" at 4011.13,7284.35 h60
  text "PTH" at 4647.77,7284.35 h60
  text "Round" at 4906.98,7284.35 h60
  text "Top Layer - Bottom Layer" at 5282.23,7284.35 h60
  text "2" at 3679.03,7160.04 h60
  text "25.00mil (0.635mm)" at 4011.13,7160.04 h60
  text "PTH" at 4647.77,7160.04 h60
  text "Round" at 4906.98,7160.04 h60
  text "Top Layer - Bottom Layer" at 5282.23,7160.04 h60
  text "40" at 3679.03,7035.73 h60
  text "39.37mil (1.000mm)" at 4011.13,7035.73 h60
  text "PTH" at 4647.77,7035.73 h60
  text "Round" at 4906.98,7035.73 h60
  text "Top Layer - Bottom Layer" at 5282.23,7035.73 h60
  text "10" at 3679.03,6911.42 h60
  text "45.28mil (1.150mm)" at 4011.13,6911.42 h60
  text "PTH" at 4647.77,6911.42 h60
  text "Round" at 4906.98,6911.42 h60
  text "Top Layer - Bottom Layer" at 5282.23,6911.42 h60
  text "4" at 3679.03,6787.11 h60
  text "51.18mil (1.300mm)" at 4011.13,6787.11 h60
  text "PTH" at 4647.77,6787.11 h60
  text "Round" at 4906.98,6787.11 h60
  text "Top Layer - Bottom Layer" at 5282.23,6787.11 h60
  text "3" at 3679.03,6662.79 h60
  text "63.00mil (1.600mm)" at 4011.13,6662.79 h60
  text "PTH" at 4647.77,6662.79 h60
  text "Round" at 4906.98,6662.79 h60
  text "Top Layer - Bottom Layer" at 5282.23,6662.79 h60
  text "2" at 3679.03,6538.48 h60
  text "66.93mil (1.700mm)" at 4011.13,6538.48 h60
  text "PTH" at 4647.77,6538.48 h60
  text "Round" at 4906.98,6538.48 h60
  text "Top Layer - Bottom Layer" at 5282.23,6538.48 h60
  text "6" at 3679.03,6414.17 h60
  text "125.98mil (3.200mm)" at 4011.13,6414.17 h60
  text "PTH" at 4647.77,6414.17 h60
  text "Round" at 4906.98,6414.17 h60
  text "Top Layer - Bottom Layer" at 5282.23,6414.17 h60
  text "2" at 3679.03,6289.86 h60
  text "21.65mil (0.550mm)" at 4011.13,6289.86 h60
  text "PTH" at 4647.77,6289.86 h60
  text "Slot" at 4906.98,6289.86 h60
  text "Top Layer - Bottom Layer" at 5282.23,6289.86 h60
  text "2" at 3679.03,6165.54 h60
  text "31.50mil (0.800mm)" at 4011.13,6165.54 h60
  text "PTH" at 4647.77,6165.54 h60
  text "Slot" at 4906.98,6165.54 h60
  text "Top Layer - Bottom Layer" at 5282.23,6165.54 h60
  text "2" at 3679.03,6041.23 h60
  text "33.47mil (0.850mm)" at 4011.13,6041.23 h60
  text "PTH" at 4647.77,6041.23 h60
  text "Slot" at 4906.98,6041.23 h60
  text "Top Layer - Bottom Layer" at 5282.23,6041.23 h60
  text "1" at 3679.03,5916.92 h60
  text "149.61mil (3.800mm)" at 4011.13,5916.92 h60
  text "PTH" at 4647.77,5916.92 h60
  text "Slot" at 4906.98,5916.92 h60
  text "Top Layer - Bottom Layer" at 5282.23,5916.92 h60
  text "1524 Total" at 3679.03,5792.61 h60
  text "Slot definitions :" at 3378.45,5705.59 h60
  text "Routed Path Length" at 3829.19,5705.59 h60
  text "= Calculated from tool start centre position to tool end centre position." at 4369.04,5705.59 h60
  text "Hole Length" at 3829.19,5655.86 h60
  text "= Routed Path Length + Tool Size = Slot length as defined in the PCB layout" at 4169.19,5655.86 h60
  text ".Layer_Name" at 577,-858.49 h60
M17 Embedded Cavity:
  text ".Layer_Name" at 577,-858.49 h60
M18 Embedded Assembly:
  text ".Layer_Name" at 577,-858.49 h60
M19 Embedded Keepout:
  text ".Layer_Name" at 577,-858.49 h60

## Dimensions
0,-400 to 1000,-400 on M2 Board Dimensions
0,0 to 0,2362.2 on M2 Board Dimensions
0,0 to 7874.02,0 on M2 Board Dimensions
